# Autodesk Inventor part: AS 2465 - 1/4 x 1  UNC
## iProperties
Comments: To add or edit properties for Autodesk Inventor files, use iProperties.
Created: 2005-06
Part Number: AS 2465 - 1/4 x 1  UNC
Vendor: Autodesk Inc.
Document SubType Name: Modeling
Designer: John Blackburn
Material: Default
Description: Hex Bolt
Standard: AS 2465
Alert: To add or edit properties for Autodesk Inventor files, use iProperties.
Control State: 0
Master: False
Checked Out: False
Shininess: 64.0
Length Units: 11272
Angle Units: 11279
Time Units: 11290
Mass Units: 11286
Length Display Precision: 3
Angle Display Precision: 2
Compacted: True
EGR: 3
Density: 0.0
Volumn: 0.0
Area: 0.0
PropertySet Name: Model Information
Author: John Blackburn
Revision Number: 8
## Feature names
1. Body [Revolution]
2. Head [Extrusion]
3. Chamfer1 [Revolution]
4. Chamfer2
